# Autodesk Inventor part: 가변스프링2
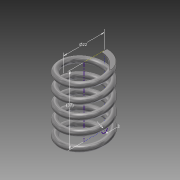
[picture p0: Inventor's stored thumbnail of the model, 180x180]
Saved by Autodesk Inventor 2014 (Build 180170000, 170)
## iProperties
Created: 2015-02
Part Number: 가변스프링2
Material: 강철, 탄소
Document SubType Name: Modeling
Designer: basic
Density: 7.87 g/cm^3
Appearance: 반연마
Mass: 18.6318 g
Surface Area: 32.4192 cm^2
Volume: 2.36745 cm^3
Author: basic
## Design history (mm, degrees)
sketch "스케치1"
  geometry: L1 (0, 0)-(11, 0); L2 (11, 0)-(11, 40.095); L3 (11, 40.095)-(0, 40.095); L4 (0, 40.095)-(0, 0); C1 r 1.5 at (11, 0)
  constraints: 8 end point, 2 parallel, 1 centre point, 1 coincident, 1 horizontal, 1 perpendicular
  dimensions: "d0" = 22 diameter of L2 L4; "d1" = 40.0955 distance of L3.end L1.start (derived); "d2" = 3 diameter of C1
feature "코일1" sketch "스케치1" pitch "d3" = 10; turns "d5" = 5; dims "d4" = 40.0955 (= d1), "d6" = 0, angle "d7" = 90 deg, angle "d8" = 90 deg, "d9" = 0, "d10" = 0
sketch "스케치2"
  geometry: L1 (0, 12.5)-(0, 9.5) reference; L2 (0, 12.5)-(0, 9.5) reference; 1 further point
  constraints: 2 vertical alignment
extrude "돌출1" cut sketch "스케치2" stored distance "d11" = 10; taper "d12" = 0 deg
node "작업 평면1"
sketch "스케치3"
  geometry: L1 (1.5, 0)-(-1.5, 0) reference; 1 further point
  constraints: 1 horizontal alignment
extrude "돌출2" cut sketch "스케치3" stored distance "d14" = 10; taper "d15" = 0 deg
node "솔리드1"
node "절단 모서리 투영1"
node "절단 모서리 투영2"
node "절단 모서리 투영3"
other parameters: "d13" = 0
